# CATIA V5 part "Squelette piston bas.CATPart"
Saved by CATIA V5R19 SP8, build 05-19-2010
Part number: Squelette piston bas
Publications: "Droite F (piston bas)", "Droite G (piston bas)", "Droite GH (piston bas)", "Droite FG (piston bas)", "Plan.3", "Plan.1", "Point.5", "Plan.4", "Plan.5", "Plan.2"
Bounding box of the stored display mesh (mm): x -62 to 12, y -104 to 70, z -50 to 50
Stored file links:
  G:\EU_thinkMotion\CFAO_2010\MMS_groupe3\MMS_groupe3\A reprendre\lpastor\lpastor\Squelette piston bas.CATPart
  C:\Users\Loïc\Documents\IFMA\Cours 2A\CFAO\Thinkmotion\Fourche avant.CATProduct
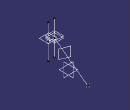
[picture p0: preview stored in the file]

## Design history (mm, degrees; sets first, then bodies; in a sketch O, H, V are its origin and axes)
Set1
  Point1 "F": linked copy from another document
  Point2 "G": linked copy from another document
  Point3 "H": linked copy from another document
Set2 "Set géométrique piston bas"
  Line1 "Droite F (piston bas)": type PtDir, RefPoint Point1, Direction xy-plane, Start -50, End 50
  Line2 "Droite G (piston bas)": type PtDir, RefPoint Point2, Direction xy-plane, Start -50, End 50
  Line3 "Droite GH (piston bas)": type PtPt, FirstPoint Point2, SecondPoint Point3
  Line4 "Droite FG (piston bas)": type PtPt, FirstPoint Point1, SecondPoint Point2
  Point4: type OnCurve, Support Line1, RefPoint Point1, Length 9
  Plane1: type Normal, Curve Line3, RefPoint Point3
  Plane2: type Normal, Curve Line2, RefPoint Point2
  Plane3: type Offset, RefPlane Plane2, Offset 5
  Plane4: type Offset, RefPlane Plane1, Offset -130
  Plane5: type Normal, Curve Line1, RefPoint Point4
Body1 (main body)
